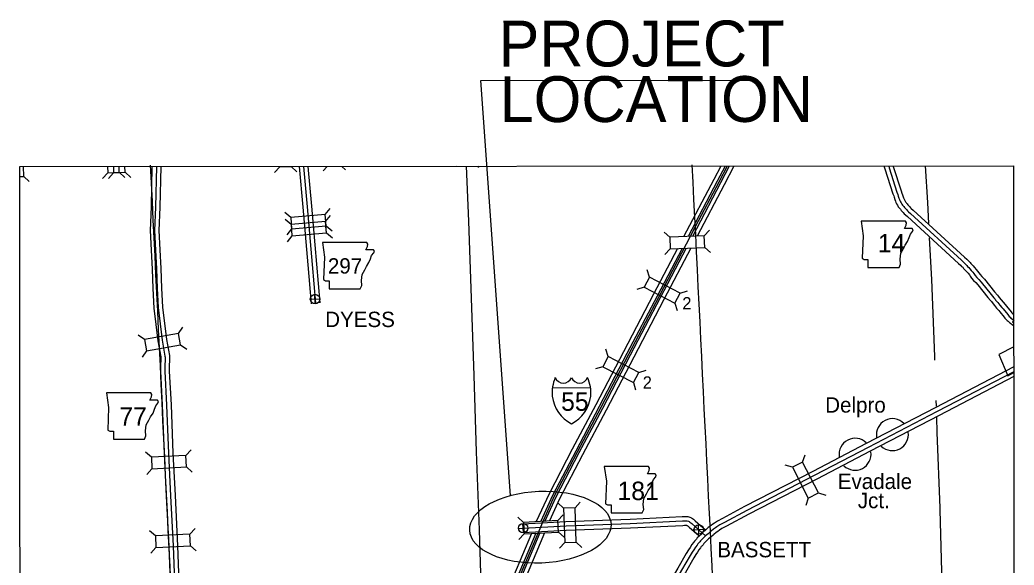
# Model space of a CAD drawing. Extents: x 2520745 to 2582119, y -1491628 to -1461664.
# Drawn here: x 2520745 to 2532127, y -1467904 to -1461664 of the extents above; entities that cross this region are included whole.
import ezdxf

# ---------------------------------------------------------------- set-up
doc = ezdxf.new("R2010")
doc.units = 0
for name, color, linetype in [('1', 7, 'Continuous'), ('10', 7, 'Continuous'), ('15', 7, 'Continuous'), ('19', 7, 'Continuous'), ('2', 7, 'Continuous'), ('20', 7, 'Continuous'), ('21', 7, 'Continuous'), ('23', 7, 'Continuous'), ('24', 7, 'Continuous'), ('26', 7, 'Continuous'), ('4', 7, 'Continuous'), ('59', 7, 'Continuous'), ('6', 7, 'Continuous'), ('60', 7, 'Continuous'), ('R_Draft', 7, 'Continuous')]:
    doc.layers.add(name, color=color, linetype=linetype)

msp = doc.modelspace()

# ---------------------------------------------------------------- linework, layer by layer
at = {"layer": '1'}
for p, q in [((2526020, -1462357), (2529146, -1462355)), ((2526362, -1467108), (2526020, -1462357))]:
    msp.add_line(p, q, dxfattribs=at)
msp.add_lwpolyline([(2520745, -1463343), (2532121, -1463336), (2532127, -1472046), (2520750, -1472053)], close=True, dxfattribs=at)
at = {"layer": '10'}
for points in [[(2522257, -1463342), (2522247, -1463805), (2522235, -1464074), (2522246, -1464301), (2522259, -1464516), (2522268, -1464740), (2522279, -1464962), (2522325, -1465338), (2522357, -1465519), (2522358, -1465531), (2522359, -1465541), (2522359, -1465554), (2522359, -1465569), (2522355, -1465595), (2522355, -1465685), (2522375, -1466074), (2522396, -1466629), (2522421, -1467114), (2522450, -1467687), (2522465, -1468096)], [(2522357, -1463342), (2522347, -1463808), (2522335, -1464074), (2522346, -1464296), (2522358, -1464511), (2522368, -1464735), (2522379, -1464953), (2522424, -1465323), (2522456, -1465505), (2522457, -1465521), (2522459, -1465535), (2522459, -1465553), (2522459, -1465576), (2522455, -1465603), (2522455, -1465683), (2522475, -1466070), (2522496, -1466624), (2522521, -1467109), (2522550, -1467683), (2522565, -1468096)], [(2523942, -1463341), (2523983, -1463806), (2524041, -1464469)], [(2524042, -1463341), (2524083, -1463797), (2524140, -1464460)], [(2530637, -1463337), (2530640, -1463345), (2530644, -1463356), (2530648, -1463370), (2530738, -1463653), (2530748, -1463678), (2530752, -1463694), (2530761, -1463720), (2530767, -1463740), (2530774, -1463753), (2530781, -1463769), (2530790, -1463784), (2530801, -1463802), (2530810, -1463814), (2530817, -1463823), (2530825, -1463832), (2530834, -1463844), (2530849, -1463861), (2530856, -1463868), (2530869, -1463884), (2530884, -1463897), (2530906, -1463916), (2531491, -1464451), (2531514, -1464473), (2531525, -1464485), (2531538, -1464496), (2531547, -1464508), (2531558, -1464519), (2531570, -1464533), (2531584, -1464547), (2531599, -1464564), (2531615, -1464583), (2531625, -1464597), (2531640, -1464619), (2531663, -1464648), (2531687, -1464670), (2531712, -1464698), (2531826, -1464840), (2531858, -1464876), (2531867, -1464888), (2531874, -1464900), (2531901, -1464932), (2531925, -1464962), (2531950, -1464989), (2531964, -1465004), (2532013, -1465066), (2532022, -1465078), (2532034, -1465093), (2532047, -1465103), (2532059, -1465114), (2532074, -1465126), (2532086, -1465137), (2532123, -1465164)], [(2530742, -1463337), (2530744, -1463341), (2530832, -1463619), (2530843, -1463646), (2530848, -1463665), (2530856, -1463689), (2530860, -1463702), (2530864, -1463710), (2530870, -1463722), (2530876, -1463733), (2530884, -1463746), (2530890, -1463754), (2530895, -1463760), (2530901, -1463768), (2530911, -1463779), (2530923, -1463793), (2530931, -1463801), (2530942, -1463815), (2530950, -1463822), (2530972, -1463841), (2531560, -1464379), (2531584, -1464402), (2531594, -1464412), (2531610, -1464427), (2531622, -1464442), (2531631, -1464451), (2531643, -1464464), (2531658, -1464480), (2531674, -1464499), (2531693, -1464520), (2531707, -1464540), (2531721, -1464560), (2531737, -1464580), (2531758, -1464600), (2531788, -1464633), (2531903, -1464776), (2531935, -1464813), (2531949, -1464830), (2531955, -1464841), (2531978, -1464869), (2532001, -1464896), (2532024, -1464921), (2532040, -1464940), (2532092, -1465005), (2532100, -1465016), (2532105, -1465021), (2532112, -1465027), (2532122, -1465036)], [(2524041, -1464469), (2524079, -1464912)], [(2524140, -1464460), (2524179, -1464904)], [(2526502, -1467431), (2526995, -1467405), (2527730, -1467379), (2528327, -1467349), (2528347, -1467347), (2528362, -1467347), (2528379, -1467348), (2528391, -1467349), (2528416, -1467355), (2528432, -1467363), (2528444, -1467370), (2528457, -1467380), (2528469, -1467389), (2528476, -1467397), (2528595, -1467502)], [(2526507, -1467530), (2526999, -1467505), (2527734, -1467479), (2528334, -1467449), (2528353, -1467447), (2528360, -1467447), (2528372, -1467447), (2528375, -1467448), (2528380, -1467449), (2528384, -1467451), (2528388, -1467454), (2528395, -1467459), (2528403, -1467465), (2528408, -1467470), (2528517, -1467567)]]:
    msp.add_lwpolyline(points, dxfattribs=at)
at = {"layer": '15'}
for points in [[(2532123, -1465635), (2531222, -1466103), (2530432, -1466513), (2529822, -1466832), (2529042, -1467234), (2528790, -1467370), (2528730, -1467401), (2528696, -1467424), (2528678, -1467436), (2528658, -1467451), (2528626, -1467474), (2528612, -1467486)], [(2532123, -1465747), (2531268, -1466191), (2530479, -1466602), (2529868, -1466920), (2529089, -1467322), (2528836, -1467459), (2528781, -1467487), (2528753, -1467506), (2528736, -1467518), (2528717, -1467532), (2528688, -1467553), (2528680, -1467560)], [(2528612, -1467486), (2528591, -1467507), (2528560, -1467530), (2528535, -1467557), (2528516, -1467576), (2528500, -1467593), (2528489, -1467607), (2528479, -1467618), (2528467, -1467630), (2528457, -1467646), (2528438, -1467670), (2528418, -1467701), (2528398, -1467729), (2528374, -1467770), (2528276, -1467938), (2527904, -1468575), (2527607, -1469072), (2527509, -1469238)], [(2528680, -1467560), (2528658, -1467582), (2528628, -1467605), (2528607, -1467627), (2528587, -1467646), (2528576, -1467658), (2528566, -1467671), (2528552, -1467687), (2528545, -1467693), (2528537, -1467705), (2528519, -1467728), (2528501, -1467756), (2528482, -1467784), (2528460, -1467821), (2528363, -1467988), (2527990, -1468626), (2527693, -1469124), (2527614, -1469256)]]:
    msp.add_lwpolyline(points, dxfattribs=at)
at = {"layer": '19'}
for points in [[(2528768, -1463338), (2528689, -1463490), (2528343, -1464146)], [(2528819, -1463338), (2528729, -1463511), (2528396, -1464144)], [(2528866, -1463338), (2528766, -1463530), (2528444, -1464142)], [(2528918, -1463338), (2528807, -1463551), (2528497, -1464139)], [(2528426, -1464275), (2528117, -1464865), (2527773, -1465524), (2527455, -1466131), (2527185, -1466641), (2526923, -1467146), (2526807, -1467398)], [(2528273, -1464281), (2527999, -1464803), (2527654, -1465462), (2527337, -1466069), (2527067, -1466579), (2526803, -1467088), (2526656, -1467406)], [(2528325, -1464279), (2528039, -1464825), (2527695, -1465483), (2527377, -1466090), (2527108, -1466600), (2526844, -1467108), (2526708, -1467403)], [(2528373, -1464277), (2528076, -1464844), (2527732, -1465503), (2527414, -1466110), (2527145, -1466620), (2526882, -1467126), (2526755, -1467401)], [(2526601, -1467541), (2526397, -1468030), (2526134, -1468655), (2525964, -1469058)], [(2526652, -1467538), (2526439, -1468047), (2526176, -1468673), (2526012, -1469062)], [(2526698, -1467536), (2526477, -1468063), (2526215, -1468689), (2526055, -1469066)], [(2526749, -1467533), (2526520, -1468081), (2526257, -1468707), (2526103, -1469070)]]:
    msp.add_lwpolyline(points, dxfattribs=at)
at = {"layer": '20'}
for p, q in [((2523719, -1463346), (2523659, -1463410)), ((2523851, -1463342), (2523915, -1463402)), ((2524264, -1463341), (2524218, -1463391)), ((2524431, -1463341), (2524474, -1463380)), ((2525742, -1463340), (2525740, -1463342)), ((2525983, -1463340), (2525996, -1463354)), ((2520789, -1463455), (2520853, -1463515)), ((2521751, -1463414), (2521692, -1463479)), ((2521751, -1463414), (2521814, -1463411)), ((2521818, -1463415), (2521759, -1463480)), ((2521883, -1463408), (2521948, -1463467)), ((2521950, -1463408), (2522015, -1463467)), ((2523845, -1463925), (2523778, -1463868)), ((2524240, -1463891), (2524296, -1463823)), ((2524243, -1463972), (2524300, -1463904)), ((2523849, -1464006), (2523782, -1463949)), ((2524255, -1464103), (2524248, -1464027)), ((2524251, -1464022), (2524318, -1464079)), ((2523856, -1464056), (2523800, -1464124)), ((2523860, -1464137), (2523804, -1464205)), ((2524255, -1464103), (2524322, -1464160)), ((2528184, -1464152), (2528120, -1464093)), ((2528580, -1464136), (2528640, -1464071)), ((2528586, -1464268), (2528650, -1464328)), ((2528190, -1464284), (2528130, -1464349)), ((2527953, -1464608), (2527927, -1464524)), ((2527892, -1464724), (2527808, -1464751)), ((2528304, -1464791), (2528388, -1464765)), ((2528243, -1464908), (2528269, -1464992)), ((2522561, -1465253), (2522612, -1465181)), ((2522171, -1465323), (2522099, -1465273)), ((2522585, -1465383), (2522657, -1465433)), ((2522195, -1465453), (2522144, -1465525)), ((2527478, -1465516), (2527452, -1465432)), ((2527417, -1465633), (2527333, -1465659)), ((2527829, -1465699), (2527913, -1465673)), ((2527768, -1465816), (2527794, -1465900)), ((2522250, -1466669), (2522184, -1466610)), ((2522645, -1466649), (2522704, -1466583)), ((2529706, -1466725), (2529733, -1466641)), ((2522652, -1466781), (2522717, -1466839)), ((2529589, -1466785), (2529505, -1466759)), ((2522257, -1466801), (2522198, -1466866)), ((2529888, -1467077), (2529972, -1467104)), ((2526968, -1467251), (2526904, -1467191)), ((2527100, -1467247), (2527160, -1467182)), ((2529770, -1467137), (2529744, -1467221)), ((2526905, -1467395), (2526964, -1467330)), ((2526509, -1467416), (2526444, -1467357)), ((2522296, -1467571), (2522230, -1467512)), ((2522691, -1467551), (2522750, -1467486)), ((2526516, -1467548), (2526458, -1467613)), ((2526912, -1467527), (2526977, -1467586)), ((2522698, -1467683), (2522763, -1467742)), ((2526983, -1467647), (2526923, -1467711)), ((2527114, -1467642), (2527179, -1467702)), ((2522302, -1467703), (2522243, -1467768))]:
    msp.add_line(p, q, dxfattribs=at)
for points in [[(2520745, -1463456), (2520789, -1463455), (2520785, -1463343)], [(2521747, -1463342), (2521751, -1463414), (2521883, -1463408), (2521880, -1463342)], [(2521815, -1463342), (2521818, -1463415), (2521950, -1463408), (2521947, -1463342)], [(2523719, -1463341), (2523719, -1463346), (2523851, -1463342), (2523851, -1463341)]]:
    msp.add_lwpolyline(points, dxfattribs=at)
for points in [[(2524240, -1463891), (2523845, -1463925), (2523856, -1464056), (2524251, -1464022)], [(2524243, -1463972), (2523849, -1464006), (2523860, -1464137), (2524255, -1464103)], [(2528190, -1464284), (2528586, -1464268), (2528580, -1464136), (2528184, -1464152)], [(2528304, -1464791), (2527953, -1464608), (2527892, -1464724), (2528243, -1464908)], [(2522195, -1465453), (2522585, -1465383), (2522561, -1465253), (2522171, -1465323)], [(2527417, -1465633), (2527768, -1465816), (2527829, -1465699), (2527478, -1465516)], [(2522257, -1466801), (2522652, -1466781), (2522645, -1466649), (2522250, -1466669)], [(2529589, -1466785), (2529770, -1467137), (2529888, -1467077), (2529706, -1466725)], [(2526968, -1467251), (2526983, -1467647), (2527114, -1467642), (2527100, -1467247)], [(2526516, -1467548), (2526912, -1467527), (2526905, -1467395), (2526509, -1467416)], [(2522691, -1467551), (2522296, -1467571), (2522302, -1467703), (2522698, -1467683)]]:
    msp.add_lwpolyline(points, close=True, dxfattribs=at)
at = {"layer": '21'}
for points in [[(2530375, -1463968), (2530400, -1464137), (2530389, -1464393), (2530412, -1464407), (2530454, -1464407), (2530454, -1464498), (2530809, -1464497), (2530826, -1464461), (2530821, -1464402), (2530829, -1464334), (2530860, -1464280), (2530880, -1464241), (2530908, -1464199), (2530925, -1464153), (2530939, -1464117), (2530964, -1464086), (2530970, -1464066), (2530959, -1464052), (2530871, -1464052), (2530891, -1464012), (2530894, -1463987), (2530882, -1463968)], [(2524208, -1464211), (2524233, -1464381), (2524222, -1464637), (2524245, -1464651), (2524287, -1464651), (2524287, -1464741), (2524642, -1464741), (2524659, -1464705), (2524654, -1464645), (2524662, -1464578), (2524693, -1464524), (2524713, -1464485), (2524741, -1464442), (2524758, -1464397), (2524772, -1464361), (2524797, -1464330), (2524803, -1464310), (2524792, -1464296), (2524704, -1464296), (2524724, -1464256), (2524727, -1464231), (2524715, -1464211)], [(2521736, -1465933), (2521761, -1466102), (2521750, -1466359), (2521773, -1466373), (2521815, -1466373), (2521815, -1466463), (2522170, -1466463), (2522187, -1466426), (2522182, -1466367), (2522190, -1466299), (2522221, -1466246), (2522241, -1466206), (2522269, -1466164), (2522286, -1466119), (2522300, -1466082), (2522325, -1466051), (2522331, -1466031), (2522320, -1466017), (2522232, -1466017), (2522252, -1465978), (2522255, -1465953), (2522243, -1465933)], [(2527434, -1466776), (2527460, -1466945), (2527449, -1467202), (2527471, -1467216), (2527513, -1467216), (2527513, -1467306), (2527869, -1467306), (2527886, -1467269), (2527880, -1467210), (2527888, -1467143), (2527919, -1467089), (2527939, -1467049), (2527967, -1467007), (2527984, -1466962), (2527998, -1466925), (2528024, -1466894), (2528029, -1466875), (2528018, -1466860), (2527931, -1466861), (2527950, -1466821), (2527953, -1466796), (2527941, -1466776)]]:
    msp.add_lwpolyline(points, close=True, dxfattribs=at)
at = {"layer": '23'}
msp.add_line((2526841, -1465874), (2527278, -1465873), dxfattribs=at)
for centre, radius, start, end in [((2527247, -1465930), 410, 155.2487, 185.8211), ((2526967, -1465721), 99.9, 202.1742, 337.3697), ((2527152, -1465721), 99.9, 202.6869, 337.8823), ((2526872, -1465930), 410, 354.2355, 24.8078), ((2527240, -1465927), 403, 186.4206, 243.4853), ((2526879, -1465927), 403, 296.5712, 353.636)]:
    msp.add_arc(centre, radius, start, end, dxfattribs=at)
at = {"layer": '24'}
for centre, start, end in [((2530733, -1466411), 44.4327, 189.7276), ((2530733, -1466411), 226.1017, 8.5691), ((2530306, -1466635), 46.1233, 188.9306), ((2530306, -1466635), 226.1017, 8.0171)]:
    msp.add_arc(centre, 183, start, end, dxfattribs=at)
at = {"layer": '26'}
for p, q in [((2524127, -1464913), (2524121, -1464805)), ((2524070, -1464862), (2524178, -1464856)), ((2526509, -1467536), (2526502, -1467427)), ((2528519, -1467551), (2528513, -1467443)), ((2526452, -1467485), (2526560, -1467478)), ((2528462, -1467500), (2528570, -1467494))]:
    msp.add_line(p, q, dxfattribs=at)
for centre in [(2524124, -1464859), (2526506, -1467481), (2528516, -1467497)]:
    msp.add_circle(centre, 54.2, dxfattribs=at)
at = {"layer": '4'}
for points in [[(2525852, -1463340), (2525879, -1463967), (2525911, -1464848), (2525943, -1465736), (2525970, -1466606), (2526001, -1467500), (2526029, -1468376), (2526045, -1468850)], [(2531108, -1463336), (2531136, -1463753), (2531148, -1463994)], [(2531156, -1464157), (2531181, -1464635), (2531215, -1465518), (2531216, -1465559)], [(2531231, -1466021), (2531233, -1466084)], [(2531237, -1466211), (2531243, -1466386), (2531275, -1467247), (2531276, -1467272), (2531300, -1468117), (2531301, -1468151), (2531337, -1469028), (2531338, -1469039), (2531361, -1469580)]]:
    msp.add_lwpolyline(points, dxfattribs=at)
at = {"layer": '59'}
for points in [[(2522307, -1463342), (2522297, -1463806), (2522285, -1464074), (2522296, -1464298), (2522308, -1464514), (2522318, -1464737), (2522329, -1464957), (2522374, -1465331), (2522406, -1465512), (2522408, -1465526), (2522409, -1465538), (2522409, -1465554), (2522409, -1465573), (2522405, -1465599), (2522405, -1465684), (2522425, -1466072), (2522446, -1466627), (2522471, -1467111), (2522500, -1467685), (2522515, -1468096)], [(2523992, -1463341), (2524033, -1463802), (2524090, -1464465)], [(2528843, -1463338), (2528748, -1463520), (2528477, -1464034)], [(2530690, -1463337), (2530691, -1463340), (2530696, -1463356), (2530785, -1463636), (2530796, -1463662), (2530800, -1463680), (2530808, -1463705), (2530814, -1463721), (2530819, -1463731), (2530826, -1463746), (2530833, -1463758), (2530843, -1463774), (2530850, -1463784), (2530856, -1463792), (2530863, -1463800), (2530872, -1463812), (2530886, -1463827), (2530893, -1463835), (2530906, -1463850), (2530917, -1463860), (2530939, -1463879), (2531526, -1464415), (2531549, -1464438), (2531559, -1464449), (2531574, -1464462), (2531585, -1464475), (2531594, -1464485), (2531607, -1464498), (2531621, -1464513), (2531636, -1464531), (2531654, -1464551), (2531666, -1464568), (2531680, -1464589), (2531700, -1464614), (2531723, -1464635), (2531750, -1464665), (2531865, -1464808), (2531896, -1464844), (2531908, -1464859), (2531915, -1464870), (2531940, -1464900), (2531963, -1464929), (2531987, -1464955), (2532002, -1464972), (2532053, -1465036), (2532061, -1465047), (2532069, -1465057), (2532080, -1465065), (2532091, -1465076), (2532107, -1465088), (2532118, -1465098), (2532123, -1465102)], [(2528477, -1464034), (2528058, -1464834), (2527714, -1465493), (2527396, -1466100), (2527126, -1466610), (2526863, -1467117), (2526738, -1467388), (2526458, -1468055), (2526195, -1468681), (2525695, -1469866)], [(2524090, -1464465), (2524129, -1464908)], [(2532123, -1465691), (2531245, -1466147), (2530456, -1466557), (2529845, -1466876), (2529066, -1467278), (2528813, -1467415), (2528756, -1467444), (2528725, -1467465), (2528707, -1467477), (2528687, -1467491), (2528657, -1467514), (2528646, -1467523)], [(2526505, -1467481), (2526997, -1467455), (2527732, -1467429), (2528331, -1467399), (2528350, -1467397), (2528361, -1467397), (2528375, -1467398), (2528383, -1467398), (2528398, -1467402), (2528408, -1467407), (2528416, -1467412), (2528426, -1467419), (2528436, -1467427), (2528442, -1467433), (2528594, -1467568)], [(2528646, -1467523), (2528625, -1467545), (2528594, -1467568), (2528571, -1467592), (2528552, -1467611), (2528538, -1467625), (2528527, -1467639), (2528515, -1467652), (2528506, -1467662), (2528497, -1467675), (2528478, -1467699), (2528459, -1467729), (2528440, -1467756), (2528417, -1467795), (2528320, -1467963), (2527947, -1468601), (2527650, -1469098), (2527522, -1469313)], [(2528646, -1467523), (2528625, -1467545), (2528594, -1467568), (2528571, -1467592), (2528552, -1467611), (2528538, -1467625), (2528527, -1467639), (2528515, -1467652), (2528506, -1467662), (2528497, -1467675), (2528478, -1467699), (2528459, -1467729), (2528440, -1467756), (2528417, -1467795), (2528320, -1467963), (2527947, -1468601), (2527650, -1469098), (2527522, -1469313)]]:
    msp.add_lwpolyline(points, dxfattribs=at)
at = {"layer": '6'}
for points in [[(2532123, -1465102), (2532108, -1465120), (2532123, -1465131)], [(2532123, -1465405), (2531951, -1465494)], [(2531951, -1465494), (2532054, -1465737), (2532123, -1465701)]]:
    msp.add_lwpolyline(points, dxfattribs=at)
at = {"layer": '60'}
for points in [[(2522661, -1472035), (2522564, -1470013), (2522242, -1463325)], [(2528873, -1472031), (2528758, -1469710), (2528442, -1463322)]]:
    msp.add_spline(points, degree=3, dxfattribs=at)
at = {"layer": 'R_Draft'}
msp.add_ellipse((2526703, -1467470), major_axis=(809, 34), ratio=0.507449, dxfattribs=at)

# ---------------------------------------------------------------- texts
at = {"layer": '2'}
for s, p in [('PROJECT', (2526224, -1462198)), ('LOCATION', (2526236, -1462834))]:
    msp.add_text(s, height=525, rotation=0.0349, dxfattribs=at).set_placement(p)
at = {"layer": '20'}
for p in [(2528328, -1464978), (2527875, -1465885)]:
    msp.add_text('2', height=141, dxfattribs=at).set_placement(p)
at = {"layer": '21'}
for s, height, p in [('14', 211.2, (2530567, -1464326)), ('297', 176, (2524271, -1464568)), ('77', 211.2, (2521884, -1466308)), ('181', 211.2, (2527587, -1467160))]:
    msp.add_text(s, height=height, dxfattribs=at).set_placement(p)
at = {"layer": '23'}
msp.add_text('55', height=211.2, dxfattribs=at).set_placement((2526941, -1466138))
at = {"layer": '24'}
for s, p in [('Delpro', (2529964, -1466159)), ('Evadale', (2530108, -1467034)), ('Jct.', (2530337, -1467253))]:
    msp.add_text(s, height=176, dxfattribs=at).set_placement(p)
at = {"layer": '6'}
for s, p in [('DYESS', (2524240, -1465180)), ('BASSETT', (2528729, -1467815))]:
    msp.add_text(s, height=176, dxfattribs=at).set_placement(p)

doc.saveas('drawing.dxf')
